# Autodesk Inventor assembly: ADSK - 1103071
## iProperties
Shininess: 50.0
Length Units: 11272
Angle Units: 11279
Time Units: 11290
Mass Units: 11286
Length Display Precision: 4
Angle Display Precision: 2
Compacted: True
Created: 2000-08
Part Number: ADSK - 1103071
Document SubType Name: Assembly
Description: 2 SHOE FLYWHEEL
Mass: 8.46348 g
Surface Area: 28.0302 cm^2
Volume: 3.12305 cm^3
Density: 2.71 g/cm^3
Density: 0.0
Volumn: 0.0
Area: 0.0
PropertySet Name: Model Information
Control State: 0
Master: False
Checked Out: False
